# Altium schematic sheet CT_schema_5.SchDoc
size 293 x 258 mm
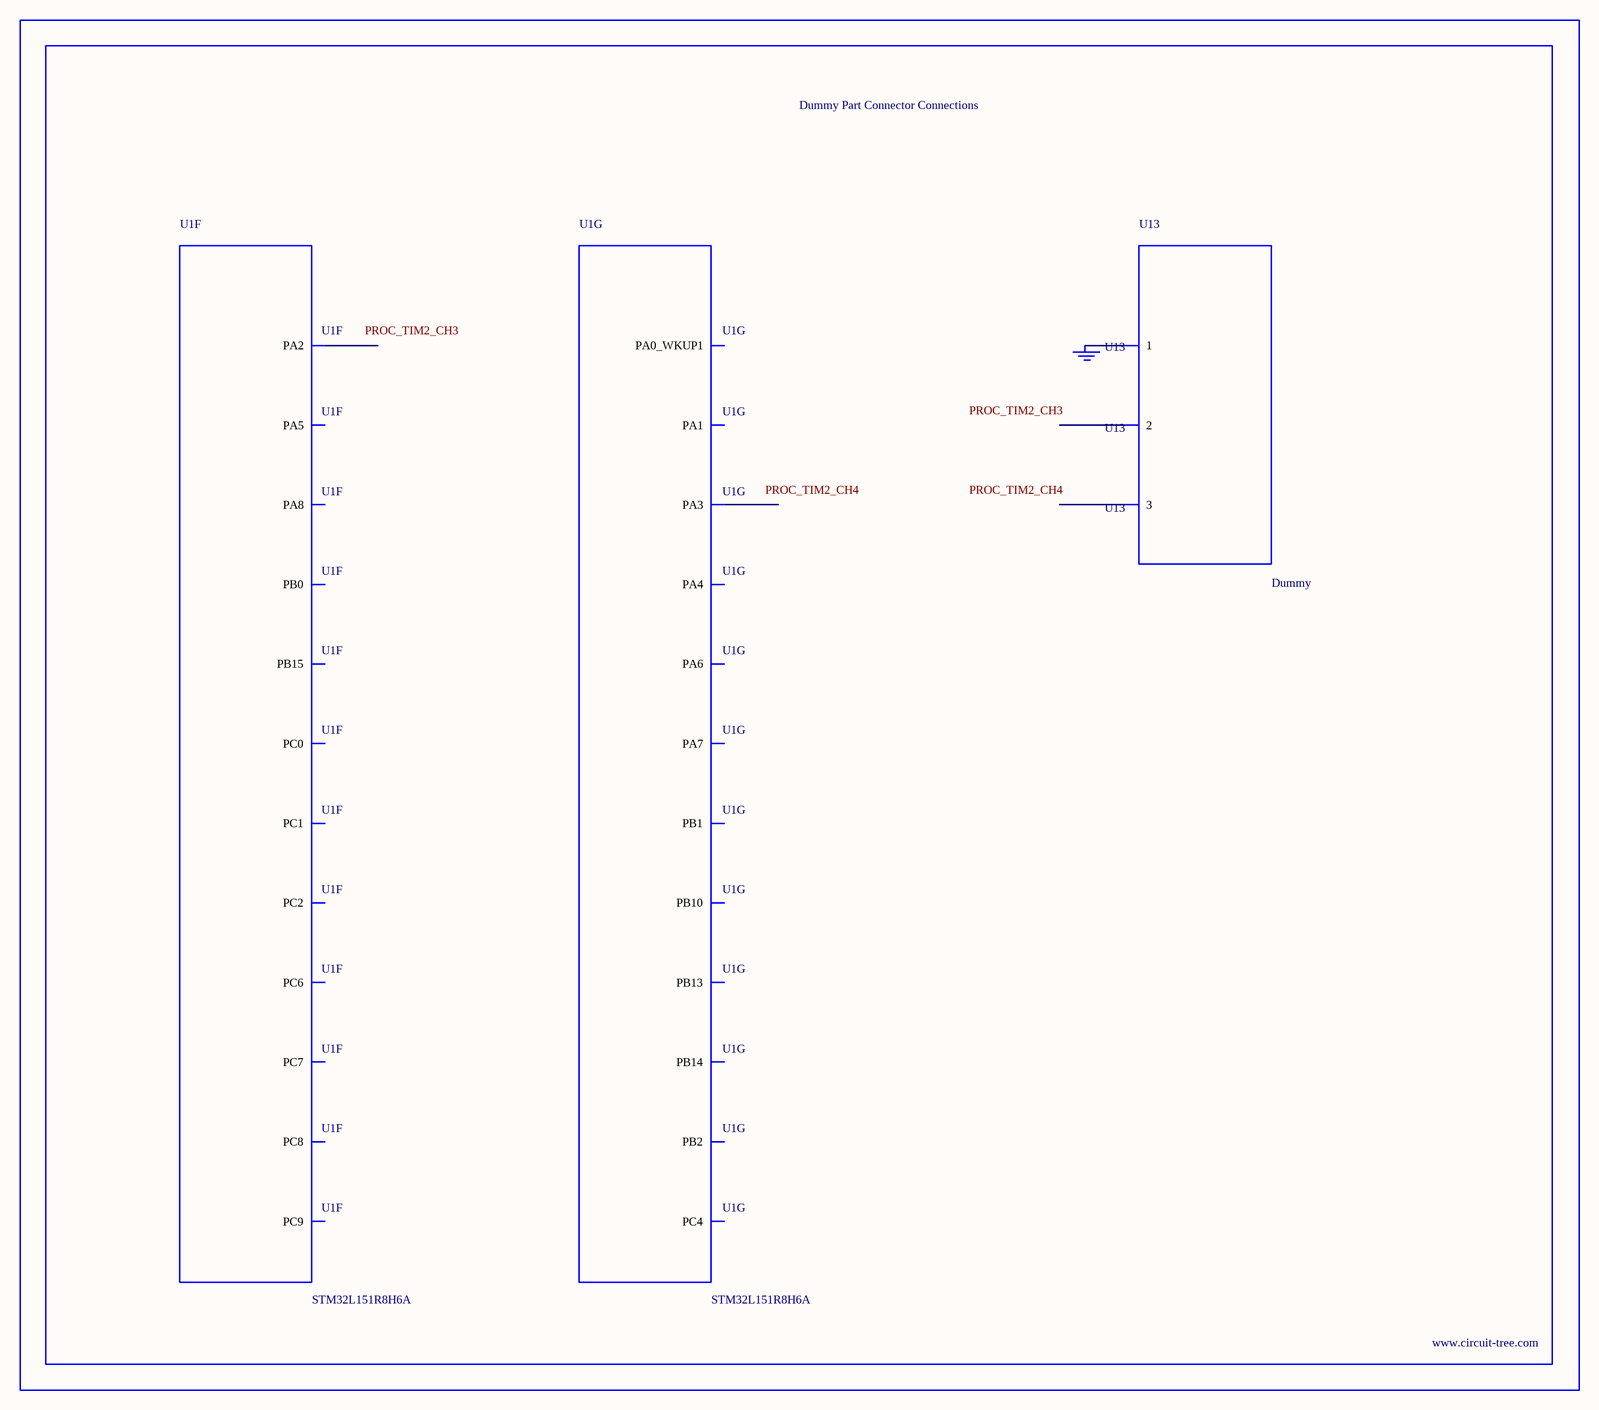
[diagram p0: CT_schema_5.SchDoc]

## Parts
BORDER4  (no value)
GND_INSTANCE_4_0  (no value)
U1  STM32L151R8H6A  [TFBGA64]  (parts F,G of 7)
U13  Dummy  [DUMMY_PACKAGE_111]

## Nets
NetGND_INSTANCE_4_0_0: GND_INSTANCE_4_0.0(GND) U13.1

Not connected (* = marked no-connect by the designer): U1 D7(PA8) D8(PC9) E2(PC1) E3(PC0) E7(PC7) E8(PC8) F2(PC2) F3(PA2) F4(PA5) F5(PB0) F6(PC6) F7(PB15) F8(PB14) G2(PA0_WKUP1) G3(PA3) G4(PA6) G5(PB1) G6(PB2) G7(PB10) G8(PB13) H2(PA1) H3(PA4) H4(PA7) H5(PC4); U13 2 3

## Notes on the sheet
- Labels drawn without touching a wire or pin: PROC_TIM2_CH3, PROC_TIM2_CH4

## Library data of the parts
BORDER4 = BORDER_PAGE4
GND_INSTANCE_4_0 = GND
